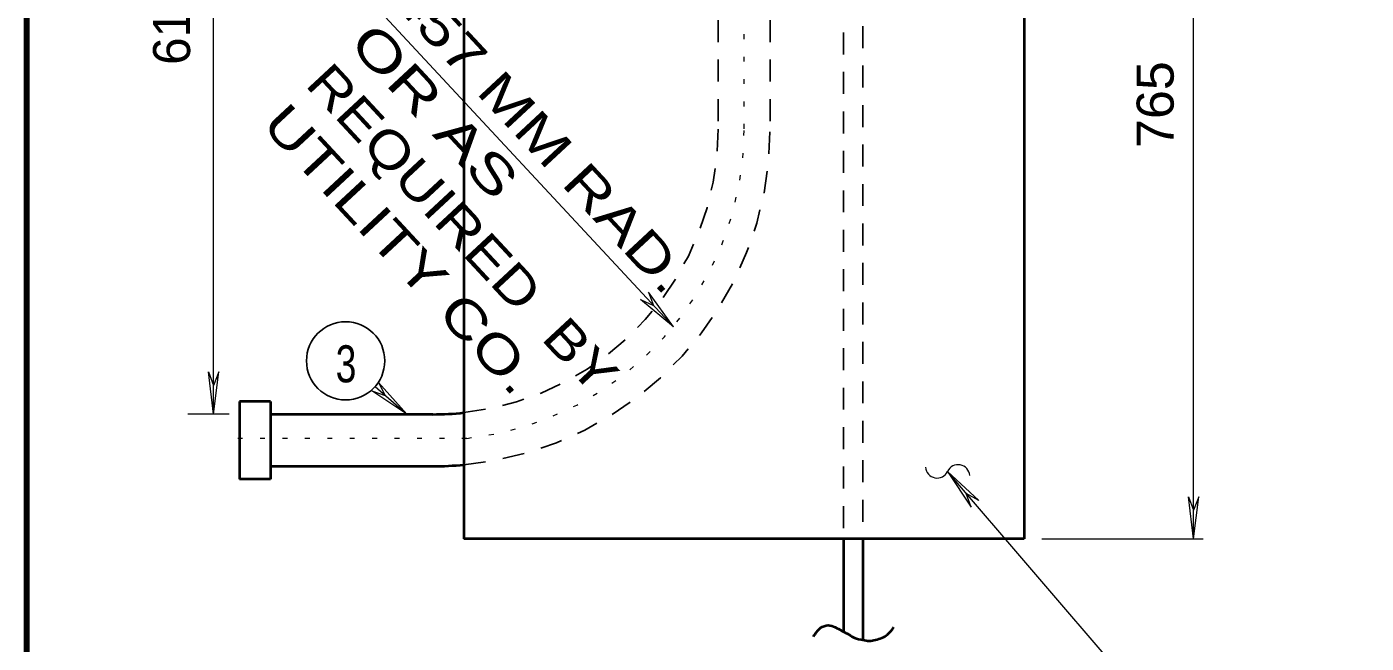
# Model space of a CAD drawing. Extents: x 312583 to 312854, y 144419 to 144597.
# Drawn here: x 312616.5 to 312643.98, y 144524.62 to 144537.27 of the extents above; entities that cross this region are included whole.
import ezdxf

# ---------------------------------------------------------------- set-up
doc = ezdxf.new("R2010")
doc.units = 0
doc.header["$LTSCALE"] = 0.3
doc.linetypes.add('DOTTED', pattern=[1.5, 0.3, -1.2])
doc.linetypes.add('SHORT_DASHED', pattern=[2.7, 1.5, -1.2])
doc.layers.add('1', color=7, linetype='Continuous', lineweight=25)
doc.layers.add('2', color=7, linetype='Continuous', lineweight=13)

msp = doc.modelspace()

# ---------------------------------------------------------------- linework, layer by layer
at = {"layer": '1', "linetype": 'DOTTED', "lineweight": 13}
for p, q in [((312631.2163, 144535.178), (312631.2163, 144546.632)), ((312625.5276, 144528.8224), (312620.6133, 144528.8224))]:
    msp.add_line(p, q, dxfattribs=at)
at = {"layer": '1', "lineweight": 40}
for p, q in [((312625.4663, 144545.2904), (312625.4663, 144526.76)), ((312636.9663, 144545.2904), (312636.9663, 144526.76)), ((312620.8663, 144529.5814), (312620.8663, 144527.9867)), ((312621.5026, 144529.5814), (312620.8663, 144529.5814)), ((312621.5026, 144529.5814), (312621.5026, 144527.9867)), ((312621.5026, 144529.3207), (312624.83, 144529.3207)), ((312621.5026, 144528.255), (312624.83, 144528.255)), ((312621.5026, 144527.9867), (312620.8663, 144527.9867)), ((312636.9663, 144526.76), (312625.4663, 144526.76)), ((312633.2556, 144526.76), (312633.2556, 144524.874)), ((312633.6543, 144526.76), (312633.6543, 144524.69))]:
    msp.add_line(p, q, dxfattribs=at)
at = {"layer": '1', "linetype": 'SHORT_DASHED'}
for p, q in [((312633.2556, 144543.6344), (312633.2556, 144526.76)), ((312633.6543, 144543.7647), (312633.6543, 144526.76)), ((312630.6873, 144541.457), (312630.6873, 144535.178)), ((312631.753, 144541.457), (312631.753, 144535.178))]:
    msp.add_line(p, q, dxfattribs=at)
at = {"layer": '1', "lineweight": 158}
msp.add_lwpolyline([(312616.5, 144423.1446), (312616.5, 144585.0846), (312849, 144585.0846)], dxfattribs=at)
at = {"layer": '1', "linetype": 'SHORT_DASHED'}
for radius, start in [(5.8567, 276.26268), (6.9211, 275.29654)]:
    msp.add_arc((312624.83, 144535.1748), radius, start, 0, dxfattribs=at)
at = {"layer": '1', "linetype": 'DOTTED', "lineweight": 13}
msp.add_arc((312624.83, 144535.1748), 6.3889, 276.26268, 0, dxfattribs=at)
at = {"layer": '1', "lineweight": 40}
for radius, end in [(5.8567, 276.26268), (6.9211, 275.29654)]:
    msp.add_arc((312624.83, 144535.1748), radius, 270, end, dxfattribs=at)
msp.add_spline([(312632.6423, 144524.759), (312632.788, 144524.9354), (312632.9413, 144524.989), (312633.087, 144524.9507), (312633.225, 144524.874), (312633.3706, 144524.7974), (312633.4856, 144524.7284), (312633.6543, 144524.69), (312633.7846, 144524.667), (312633.915, 144524.69), (312634.1603, 144524.7974), (312634.2906, 144524.9507)], degree=3, dxfattribs=at)
at = {"layer": '2'}
for p, q in [((312640.4424, 144526.76), (312640.4424, 144545.9267)), ((312620.3325, 144529.3207), (312620.3325, 144544.654)), ((312629.7673, 144531.1147), (312621.0733, 144540.468)), ((312629.2536, 144531.8277), (312629.361, 144531.5517)), ((312629.7673, 144531.1147), (312629.2536, 144531.8277)), ((312629.0926, 144531.6744), (312629.361, 144531.5517)), ((312629.7673, 144531.1147), (312629.0926, 144531.6744)), ((312620.2251, 144530.187), (312620.3325, 144529.911)), ((312620.3325, 144529.3207), (312620.2251, 144530.187)), ((312620.4398, 144530.187), (312620.3325, 144529.911)), ((312620.3325, 144529.3207), (312620.4398, 144530.187)), ((312623.5803, 144529.8037), (312623.8563, 144529.704)), ((312624.301, 144529.3207), (312623.5803, 144529.8037)), ((312623.6493, 144529.888), (312624.301, 144529.3207)), ((312623.7183, 144529.9724), (312623.8563, 144529.704)), ((312624.301, 144529.3207), (312623.7183, 144529.9724)), ((312620.6527, 144529.3207), (312619.8063, 144529.3207)), ((312640.9587, 144521.6518), (312635.3946, 144528.1477)), ((312635.3946, 144528.1477), (312635.875, 144527.4159)), ((312635.3946, 144528.1477), (312636.036, 144527.5515)), ((312635.875, 144527.4159), (312635.7768, 144527.6949)), ((312636.036, 144527.5515), (312635.7768, 144527.6949)), ((312640.335, 144527.6264), (312640.4424, 144527.3504)), ((312640.4424, 144526.76), (312640.335, 144527.6264)), ((312640.5497, 144527.6264), (312640.4424, 144527.3504)), ((312640.4424, 144526.76), (312640.5497, 144527.6264)), ((312637.3266, 144526.76), (312640.6407, 144526.76))]:
    msp.add_line(p, q, dxfattribs=at)
at = {"layer": '2', "lineweight": 25}
msp.add_circle((312623.0424, 144530.4158), 0.8026, dxfattribs=at)
at = {"layer": '2'}
for centre, start, end in [((312635.1778, 144528.2508), 184.50975, 334.50975), ((312635.6102, 144528.0446), 4.50975, 154.50975)]:
    msp.add_arc(centre, 0.2395, start, end, dxfattribs=at)

# ---------------------------------------------------------------- texts
msp.add_text('610', height=0.76, rotation=90, dxfattribs=at).set_placement((312619.8513, 144536.489))
for s, rotation, width, p in [('457 MM RAD.', 312.909, 1.3, (312623.9491, 144537.8022)), ('OR AS ', 312.91, 1.4, (312623.0827, 144536.9061)), ('REQUIRED  BY', 312.91, 1.2, (312622.1891, 144536.0754)), ('765', 90, 1.05, (312640.0326, 144534.7846)), ('UTILITY CO.', 312.91, 1.3, (312621.2955, 144535.2448))]:
    msp.add_text(s, height=0.76, rotation=rotation, dxfattribs=dict(at, width=width)).set_placement(p)
at = {"layer": '2', "width": 0.75}
msp.add_text('3', height=0.76, dxfattribs=at).set_placement((312622.8383, 144529.9748))

doc.saveas('drawing.dxf')
